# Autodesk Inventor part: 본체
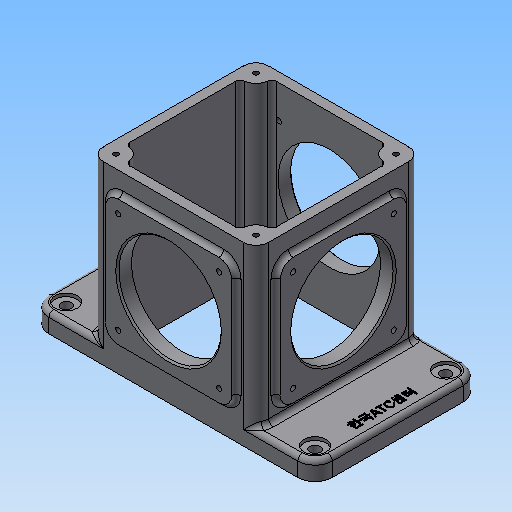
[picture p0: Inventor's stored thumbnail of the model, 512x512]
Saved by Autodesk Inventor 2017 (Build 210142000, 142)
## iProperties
Created: 2018-09
Part Number: 본체
Material: 일반
Document SubType Name: Modeling
Designer: mduedu
Density: 1 g/cm^3
Mass: 359.032 g
Surface Area: 957.184 cm^2
Volume: 359.032 cm^3
Appearance: 기본값
Author: mduedu
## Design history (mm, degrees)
sketch "스케치1"
  geometry: L1 (90, 52.5)-(-90, 52.5); L2 (-90, 52.5)-(-90, -52.5); L3 (-90, -52.5)-(90, -52.5); L4 (90, -52.5)-(90, 52.5); L5 (90, 52.5)-(-90, -52.5); L6 (-90, 52.5)-(90, -52.5); 1 further point
  constraints: 12 end point, 2 midpoint, 2 parallel, 1 horizontal, 1 perpendicular
  dimensions: "d0" = 180 distance of L3.end L2.end; "d1" = 105 distance of L2.end L1.end
extrude "돌출1" new body sketch "스케치1" distance "d2" = 12; taper "d3" = 0 deg
sketch "스케치2"
  geometry: L1 (-52.5, -52.5)-(52.5, -52.5); L2 (52.5, -52.5)-(52.5, 52.5); L3 (52.5, 52.5)-(-52.5, 52.5); L4 (-52.5, 52.5)-(-52.5, -52.5); L5 (-52.5, -52.5)-(52.5, 52.5); L6 (52.5, -52.5)-(-52.5, 52.5); 1 further point
  constraints: 12 end point, 2 midpoint, 2 parallel, 1 horizontal, 1 perpendicular
  dimensions: "d4" = 105 distance of L3.end L2.end; "d5" = 105 distance of L2.end L1.end
extrude "돌출2" join sketch "스케치2" distance "d6" = 100; taper "d7" = 0 deg
sketch "스케치14"
  geometry: L1 (-52.5, 52.5)-(52.5, 52.5) reference; L2 (52.5, 52.5)-(52.5, -52.5) reference; L3 (52.5, -52.5)-(-52.5, -52.5) reference; L4 (-52.5, -52.5)-(-52.5, 52.5) reference; L5 (46.5, 46.5)-(-46.5, 46.5); L6 (-46.5, 46.5)-(-46.5, -46.5); L7 (-46.5, -46.5)-(46.5, -46.5); L8 (46.5, -46.5)-(46.5, 46.5); 1 further point
  constraints: 8 end point, 3 other
  dimensions: "d85" = 6 distance between parallel lines of L5 L1
extrude "돌출10" cut sketch "스케치14" stored distance "d86" = 10; taper "d87" = 0 deg
fillet "모깎기1" dims "d12" = 8
sketch "스케치15"
  geometry: A1 r 8 centre (-44.5, 44.5) between (-44.5, 52.5) and (-52.5, 44.5) reference; A2 r 8 centre (44.5, 44.5) between (52.5, 44.5) and (44.5, 52.5) reference; A3 r 8 centre (44.5, -44.5) between (44.5, -52.5) and (52.5, -44.5) reference; A4 r 8 centre (-44.5, -44.5) between (-52.5, -44.5) and (-44.5, -52.5) reference; 5 further points
  constraints: 4 coincident, 4 vertical alignment, 8 other
extrude "돌출11" join sketch "스케치15" stored distance "d88" = 10; taper "d89" = 0 deg
fillet "모깎기15" dims "d90" = 3
sketch "스케치6"
  geometry: L1 (50, 19)-(130, 19); L2 (130, 19)-(130, 99); L3 (130, 99)-(50, 99); L4 (50, 99)-(50, 19); L5 (50, 19)-(130, 99); L6 (130, 19)-(50, 99); L7 (0, 0)-(180, 0) reference; 4 further points
  constraints: 12 end point, 4 midpoint, 2 parallel, 1 horizontal, 1 perpendicular, 1 vertical alignment
  dimensions: "d25" = 80 distance of L3.end L2.end; "d26" = 80 distance of L2.end L1.end; "d27" = 59 distance of point (90, 0) point (90, 59)
extrude "돌출6" join sketch "스케치6" distance "d28" = 3; taper "d29" = 0 deg
fillet "모깎기7" dims "d30" = 8
sketch "스케치7"
  geometry: C1 r 32.5 at (90, 59); 1 further point
  constraints: 1 centre point, 1 vertical alignment
  dimensions: "d32" = 65 diameter of C1; "d33" = 59 distance of C1.centre point (90, 0)
extrude "돌출7" cut sketch "스케치7" stored distance "d34" = 3; taper "d35" = 0 deg
fillet "모깎기9" dims "d36" = 3
sketch "스케치8"
  geometry: L1 (4.5, 7)-(84.5, 7); L2 (84.5, 7)-(84.5, 87); L3 (84.5, 87)-(4.5, 87); L4 (4.5, 87)-(4.5, 7); L5 (4.5, 7)-(84.5, 87); L6 (84.5, 7)-(4.5, 87); L7 (-8, -12)-(97, -12) reference; C1 r 32.5 at (44.5, 47); 4 further points
  constraints: 12 end point, 4 midpoint, 2 parallel, 1 centre point, 1 coincident, 1 horizontal, 1 perpendicular, 1 vertical alignment
  dimensions: "d37" = 80 distance of L3.end L2.end; "d38" = 80 distance of L2.end L1.end; "d39" = 59 distance from line of point (44.5, 47) L7; "d40" = 65 diameter of C1
extrude "돌출8" join sketch "스케치8" distance "d41" = 3; taper "d42" = 0 deg
fillet "모깎기10" dims "d43" = 8
extrude "돌출9" cut sketch "스케치8" stored distance "d44" = 3; taper "d45" = 0 deg
fillet "모깎기11" dims "d46" = 3
sketch "스케치9"
  geometry: L1 (50, 91)-(50, 27) reference; L2 (58, 19)-(122, 19) reference; L3 (130, 27)-(130, 91) reference; L4 (122, 99)-(58, 99) reference; C1 r 32.5 at (90, 59) reference; A1 r 8 centre (58, 91) between (58, 99) and (50, 91) reference; A2 r 8 centre (58, 27) between (50, 27) and (58, 19) reference; A3 r 8 centre (122, 27) between (122, 19) and (130, 27) reference; A4 r 8 centre (122, 91) between (130, 91) and (122, 99) reference; 5 further points
  constraints: 4 coincident
hole "구멍1" sketch "스케치9" at (58, 91), (122, 91), (122, 27), (58, 27) diameter "d47" = 3.242; stored, may be unused: countersink angle "d51" = 90 deg, drill point angle "d53" = 118 deg; dims "d48" = 6, "d49" = 4, "d50" = 2, "d52" = 9
sketch "스케치10"
  geometry: L1 (12.5, 7)-(76.5, 7) reference; L2 (84.5, 15)-(84.5, 79) reference; L3 (76.5, 87)-(12.5, 87) reference; L4 (4.5, 79)-(4.5, 15) reference; C1 r 32.5 at (44.5, 47) reference; A1 r 8 centre (12.5, 15) between (4.5, 15) and (12.5, 7) reference; A2 r 8 centre (76.5, 15) between (76.5, 7) and (84.5, 15) reference; A3 r 8 centre (76.5, 79) between (84.5, 79) and (76.5, 87) reference; A4 r 8 centre (12.5, 79) between (12.5, 87) and (4.5, 79) reference; 5 further points
  constraints: 4 coincident
hole "구멍2" sketch "스케치10" at (12.5, 79), (76.5, 79), (76.5, 15), (12.5, 15) diameter "d54" = 3.242; stored, may be unused: countersink angle "d58" = 90 deg, drill point angle "d60" = 118 deg; dims "d55" = 6, "d56" = 4, "d57" = 2, "d59" = 9
fillet "모깎기12" dims "d68" = 11
sketch "스케치16"
  geometry: A1 r 11 centre (-79, 41.5) between (-79, 52.5) and (-90, 41.5) reference; A2 r 11 centre (-79, -41.5) between (-90, -41.5) and (-79, -52.5) reference; A3 r 11 centre (79, 41.5) between (90, 41.5) and (79, 52.5) reference; A4 r 11 centre (79, -41.5) between (79, -52.5) and (90, -41.5) reference; 5 further points
  constraints: 4 coincident
hole "구멍5" sketch "스케치16" at (-79, 41.5), (79, 41.5), (79, -41.5), (-79, -41.5) diameter "d91" = 6.6; stored, may be unused: countersink angle "d95" = 90 deg, drill point angle "d97" = 118 deg; dims "d92" = 6, "d93" = 14, "d94" = 2, "d96" = 8
fillet "모깎기13" dims "d77" = 3
fillet "모깎기14" dims "d78" = 3
chamfer "모따기1" distance "d79" = 1; stored, may be unused: second distance "d80" = 2, angle "d81" = 45 deg
sketch "스케치17"
  geometry: A1 r 8 centre (-44.5, 44.5) between (-44.5, 52.5) and (-52.5, 44.5) reference; A2 r 8 centre (-44.5, -44.5) between (-52.5, -44.5) and (-44.5, -52.5) reference; A3 r 8 centre (44.5, -44.5) between (44.5, -52.5) and (52.5, -44.5) reference; A4 r 8 centre (44.5, 44.5) between (52.5, 44.5) and (44.5, 52.5) reference; 5 further points
  constraints: 4 coincident
hole "구멍6" sketch "스케치17" at (-44.5, 44.5), (44.5, 44.5), (44.5, -44.5), (-44.5, -44.5) diameter "d98" = 3.242; stored, may be unused: countersink angle "d102" = 90 deg, drill point angle "d104" = 118 deg; dims "d99" = 8, "d100" = 15, "d101" = 2, "d103" = 10
sketch "스케치13"
  geometry: L1 (90, -41.5)-(90, 41.5) reference; 2 further points
  constraints: 1 horizontal alignment, 1 other
  dimensions: "d82" = 10 distance from line of point (80, 0) L1
feature "엠보싱1" sketch "스케치13" dims "d0" = 180, "d1" = 105, "d25" = 80, "d26" = 80, "d27" = 59, "d83" = 0.5, "d84" = 0
node "솔리드1"
mirror "대칭1"
mirror "대칭2"
node "투영된 루프2"
node "투영된 루프3"
node "투영된 루프6"
